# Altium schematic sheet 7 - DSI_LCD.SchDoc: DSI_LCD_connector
size A3; Date: 29-DEC-2018; Author: A.B; DrawnBy: CR; Address2: Austin,TX; Address3: USA; DocumentNumber: DK2 RefDes; Revision: C-01; SheetNumber: 7; SheetTotal: 14; Project: STM32MP15-DISCO PI
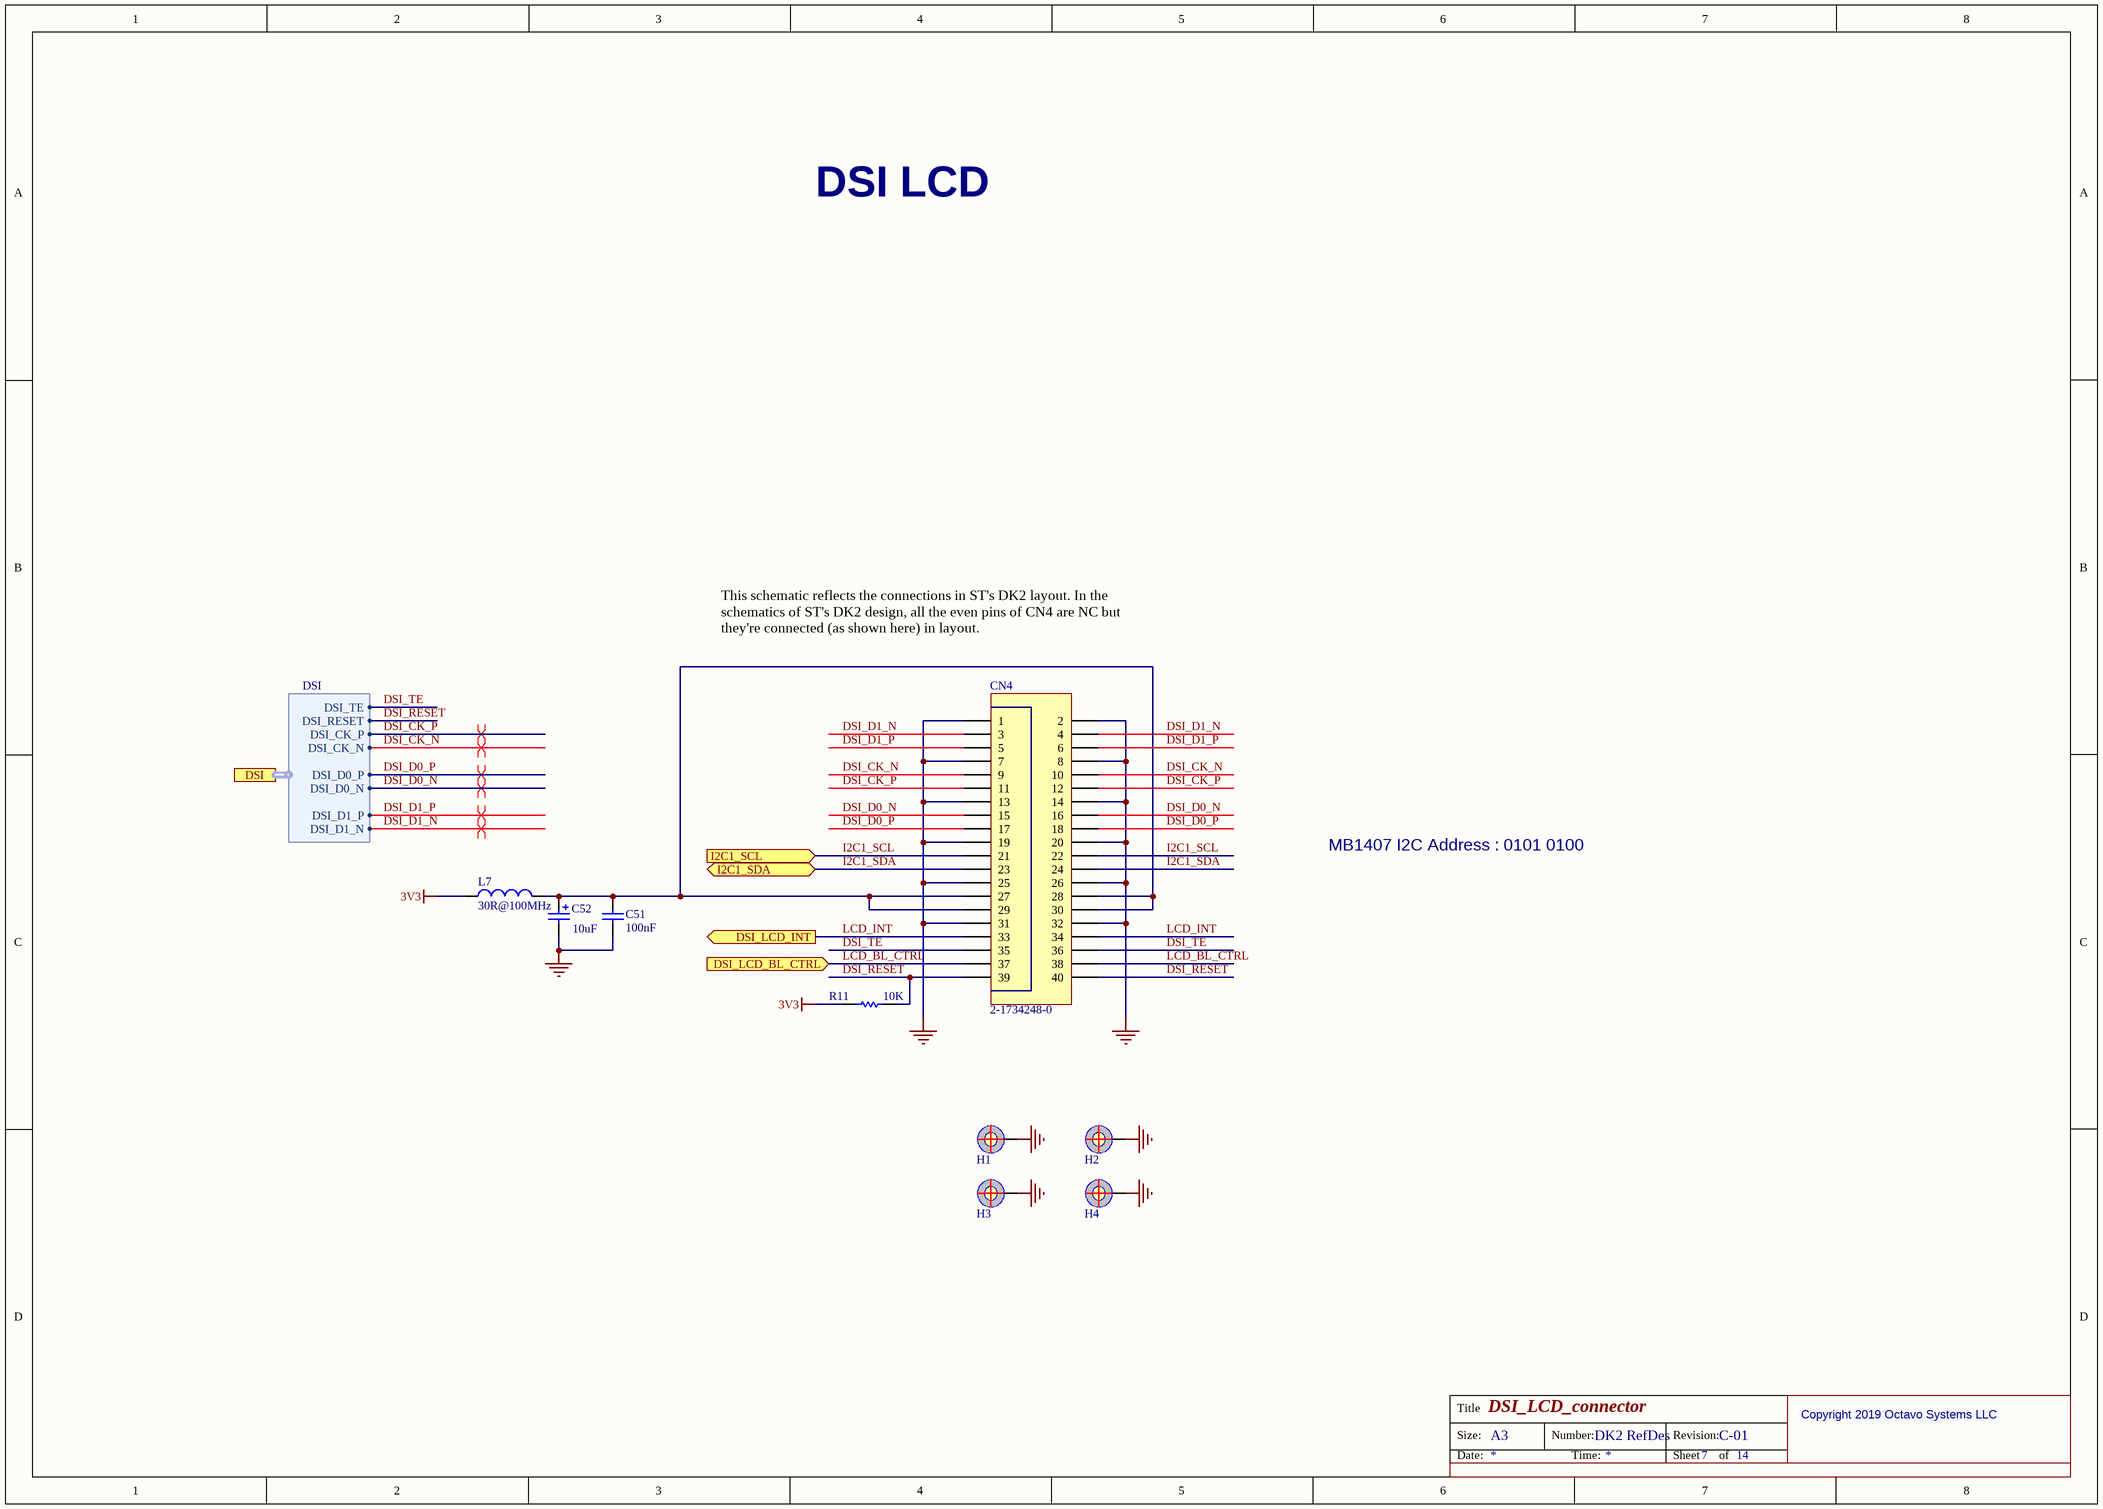
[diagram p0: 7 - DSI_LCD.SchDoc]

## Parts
C51  value 100nF  [C0402]
C52  value 10uF  [CPOL_TAJ-A_1206_H180]
CN4  value 2-1734248-0  [CON_TE-CONNECTIVITY_2-1734248-0]
H1  (no value)  [PTH_M1261-3005-N_3P5X6_M3_H14]  (no BOM)
H2  (no value)  [PTH_M1261-3005-N_3P5X6_M3_H14]  (no BOM)
H3  (no value)  [PTH_M1261-3005-N_3P5X6_M3_H14]  (no BOM)
H4  (no value)  [PTH_M1261-3005-N_3P5X6_M3_H14]  (no BOM)
L7  value 30R@100MHz  [L0603]  (hidden comment: BEAD)
R11  value 10K  [R0402]

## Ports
DSI (harness DSI), DSI_LCD_BL_CTRL (in), DSI_LCD_INT (out), I2C1_SCL (in), I2C1_SDA (bidir)

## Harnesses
DSI: DSI_CK_P, DSI_CK_N, DSI_D0_P, DSI_D0_N, DSI_D1_P, DSI_D1_N, DSI_TE, DSI_RESET

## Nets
3V3: L7.1 R11.1
GND: C51.1 C52.2 CN4.1 CN4.2 CN4.7 CN4.8 CN4.13 CN4.14 CN4.19 CN4.20 CN4.25 CN4.26 CN4.31 CN4.32 H1.1 H2.1 H3.1 H4.1
DSI_CK_N: CN4.9 CN4.10 ; port DSI.DSI_CK_N
DSI_CK_P: CN4.11 CN4.12 ; port DSI.DSI_CK_P
DSI_D0_N: CN4.15 CN4.16 ; port DSI.DSI_D0_N
DSI_D0_P: CN4.17 CN4.18 ; port DSI.DSI_D0_P
DSI_D1_N: CN4.3 CN4.4 ; port DSI.DSI_D1_N
DSI_D1_P: CN4.5 CN4.6 ; port DSI.DSI_D1_P
DSI_RESET: CN4.39 CN4.40 R11.2 ; port DSI.DSI_RESET
DSI_TE: CN4.35 CN4.36 ; port DSI.DSI_TE
I2C1_SCL: CN4.21 CN4.22 ; port I2C1_SCL
I2C1_SDA: CN4.23 CN4.24 ; port I2C1_SDA
LCD_BL_CTRL: CN4.37 CN4.38 ; port DSI_LCD_BL_CTRL
LCD_INT: CN4.33 CN4.34 ; port DSI_LCD_INT
NetC51_2: C51.2 C52.1 CN4.27 CN4.28 CN4.29 CN4.30 L7.2

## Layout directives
differential pair: DSI_CK_N, DSI_CK_P, DSI_D0_N, DSI_D0_P, DSI_D1_N, DSI_D1_P

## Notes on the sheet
- DSI LCD
- This schematic reflects the connections in ST's DK2 layout. In the schematics of ST's DK2 design, all the even pins of CN4 are NC but they're connected (as shown here) in layout.
- MB1407 I2C Address : 0101 0100
- Copyright 2019 Octavo Systems LLC

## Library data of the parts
C51 = MCD-00006: Capacitor,100nF,16V,X7R,10%,0402; Manufacturer_Part_Number: CC0402KRX7R7BB104; Manufacturer: YAGEO; Provided_By: Subcon; Initial_Board_Reference: mb1274
C52 = MCD-00199: Polarized Capacitor,10uF,16V,10%,typeA; Manufacturer_Part_Number: TAJA106K016R; Manufacturer: AVX; Provided_By: Subcon; ECCN_US: EAR99; ECCN_EU: NEC
CN4 = 2-1734248-0: Socket ,TEConn,FCC/FPC, 20pins, 1.0mm,SMT, ZIF Receptacle; Internal_Part_Number: MCD-01013; Part_Type: Connector; Manufacturer: TE CONNECTIVITY; Provided_By: Subcon; Initial_Board_Reference: MB1272
H1-H4 = MCD-00035: POSITION HOLE C6D3R5; Part_Type: Mechanical; Initial_Board_Reference: mb1274
L7 = MCD-00046: SMD Chip ferrite bead, 30R@100MHz +/-30%, 5A, 10mohm DC, S (Standard) material, 0603, T=0.8mm; Part_Type: Inductor; Manufacturer_Part_Number: MPZ1608S300A; Manufacturer: TDK; Provided_By: Subcon; Initial_Board_Reference: MB1274
R11 = MCD-00053: Resistor,10K,0402,1%,1/16W; Manufacturer_Part_Number: RC0402FR-0710KL; Manufacturer: YAGEO; Provided_By: subcon; Initial_Board_Reference: mb1274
